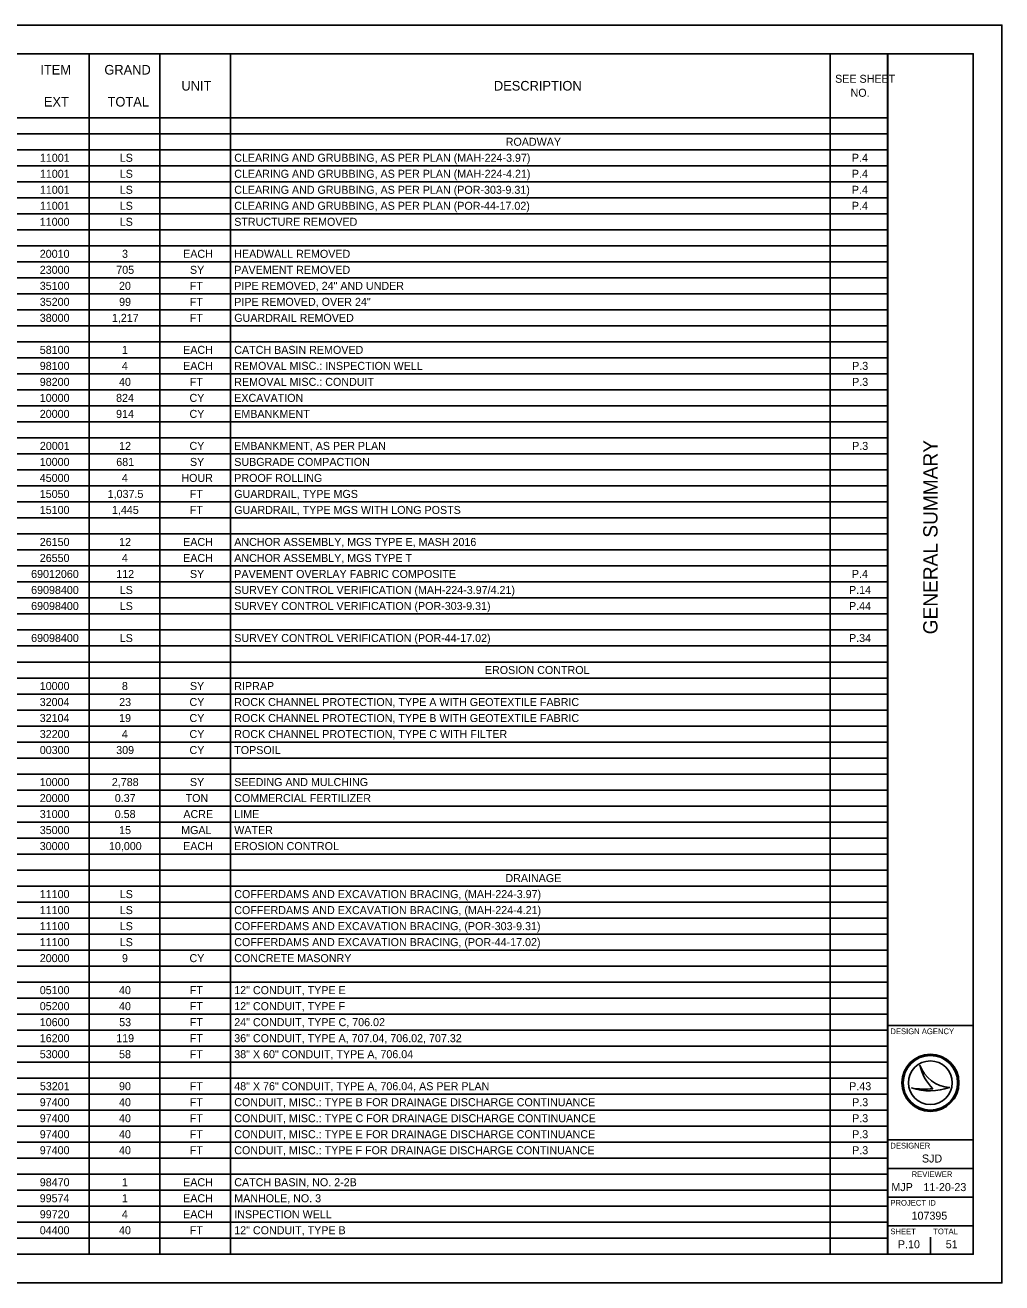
# Model space of a CAD drawing. Extents: x 0 to 34, y 0 to 22.
# Drawn here: x 16.92 to 34, y 0 to 22 of the extents above; entities that cross this region are included whole.
import ezdxf

# ---------------------------------------------------------------- set-up
doc = ezdxf.new("R2010")
doc.units = 0
for name, color, linetype in [('SH_Border', 7, 'Continuous'), ('SH_Cut_Line', 7, 'Continuous'), ('SH_Data', 7, 'Continuous'), ('SH_Text', 7, 'Continuous')]:
    doc.layers.add(name, color=color, linetype=linetype)

msp = doc.modelspace()

# ---------------------------------------------------------------- linework, layer by layer
at = {"layer": 'SH_Border'}
for p, q in [((32, 0.5), (32, 21.5)), ((32, 4.5), (33.5, 4.5)), ((32, 2.5), (33.5, 2.5)), ((32, 2), (33.5, 2)), ((32, 1.5), (33.5, 1.5)), ((32, 1), (33.5, 1))]:
    msp.add_line(p, q, dxfattribs=at)
msp.add_lwpolyline([(1.5, 21.5), (33.5, 21.5), (33.5, 0.5), (1.5, 0.5)], close=True, dxfattribs=at)
at = {"layer": 'SH_Cut_Line'}
msp.add_lwpolyline([(0, 0), (34, 0), (34, 22), (0, 22)], close=True, dxfattribs=at)
at = {"layer": 'SH_Data'}
for p, q in [((32.567, 3.81), (32.567, 3.81)), ((32.417, 3.41), (32.417, 3.41)), ((32.75, 3.5), (32.75, 3.5)), ((33.087, 3.419), (33.087, 3.419)), ((32.375, 0.675), (32.375, 0.675)), ((32.75, 0.5), (32.75, 0.8))]:
    msp.add_line(p, q, dxfattribs=at)
for radius in [0.5, 0.477, 0.477, 0.382]:
    msp.add_circle((32.75, 3.5), radius, dxfattribs=at)
for centre, radius, start, end in [((33.116, 3.998), 0.58, 198.9257, 198.9319), ((33.347, 3.97), 0.796, 191.6379, 191.6421), ((33.116, 3.998), 0.58, 198.9319, 267.1657), ((33.347, 3.97), 0.796, 191.6421, 226.0947), ((32.739, 4.37), 1.013, 251.4576, 290.0832), ((32.648, 4.654), 1.266, 259.4964, 259.4995), ((32.739, 4.37), 1.013, 251.4527, 251.4576), ((32.648, 4.654), 1.266, 259.4995, 276.6672)]:
    msp.add_arc(centre, radius, start, end, dxfattribs=at)
at = {"layer": 'SH_Text'}
for p, q in [((1.5, 21.5), (32.004, 21.5)), ((18.036, 21.5), (18.036, 0.5)), ((19.272, 21.5), (19.272, 0.5)), ((20.507, 21.5), (20.507, 0.5)), ((30.999, 21.5), (30.999, 0.5)), ((32.004, 21.5), (32.004, 0.5)), ((1.5, 20.38), (32.004, 20.38)), ((1.5, 20.1), (32.004, 20.1)), ((1.5, 19.82), (32.004, 19.82)), ((1.5, 19.54), (32.004, 19.54)), ((1.5, 19.26), (32.004, 19.26)), ((1.5, 18.98), (32.004, 18.98)), ((1.5, 18.7), (32.004, 18.7)), ((1.5, 18.42), (32.004, 18.42)), ((1.5, 18.14), (32.004, 18.14)), ((1.5, 17.86), (32.004, 17.86)), ((1.5, 17.58), (32.004, 17.58)), ((1.5, 17.3), (32.004, 17.3)), ((1.5, 17.02), (32.004, 17.02)), ((1.5, 16.74), (32.004, 16.74)), ((1.5, 16.46), (32.004, 16.46)), ((1.5, 16.18), (32.004, 16.18)), ((1.5, 15.9), (32.004, 15.9)), ((1.5, 15.62), (32.004, 15.62)), ((1.5, 15.34), (32.004, 15.34)), ((1.5, 15.06), (32.004, 15.06)), ((1.5, 14.78), (32.004, 14.78)), ((1.5, 14.5), (32.004, 14.5)), ((1.5, 14.22), (32.004, 14.22)), ((1.5, 13.94), (32.004, 13.94)), ((1.5, 13.66), (32.004, 13.66)), ((1.5, 13.38), (32.004, 13.38)), ((1.5, 13.1), (32.004, 13.1)), ((1.5, 12.82), (32.004, 12.82)), ((1.5, 12.54), (32.004, 12.54)), ((1.5, 12.26), (32.004, 12.26)), ((1.5, 11.98), (32.004, 11.98)), ((1.5, 11.7), (32.004, 11.7)), ((1.5, 11.42), (32.004, 11.42)), ((1.5, 11.14), (32.004, 11.14)), ((1.5, 10.86), (32.004, 10.86)), ((1.5, 10.58), (32.004, 10.58)), ((1.5, 10.3), (32.004, 10.3)), ((1.5, 10.02), (32.004, 10.02)), ((1.5, 9.74), (32.004, 9.74)), ((1.5, 9.46), (32.004, 9.46)), ((1.5, 9.18), (32.004, 9.18)), ((1.5, 8.9), (32.004, 8.9)), ((1.5, 8.62), (32.004, 8.62)), ((1.5, 8.34), (32.004, 8.34)), ((1.5, 8.06), (32.004, 8.06)), ((1.5, 7.78), (32.004, 7.78)), ((1.5, 7.5), (32.004, 7.5)), ((1.5, 7.22), (32.004, 7.22)), ((1.5, 6.94), (32.004, 6.94)), ((1.5, 6.66), (32.004, 6.66)), ((1.5, 6.38), (32.004, 6.38)), ((1.5, 6.1), (32.004, 6.1)), ((1.5, 5.82), (32.004, 5.82)), ((1.5, 5.54), (32.004, 5.54)), ((1.5, 5.26), (32.004, 5.26)), ((1.5, 4.98), (32.004, 4.98)), ((1.5, 4.7), (32.004, 4.7)), ((1.5, 4.42), (32.004, 4.42)), ((1.5, 4.14), (32.004, 4.14)), ((1.5, 3.86), (32.004, 3.86)), ((1.5, 3.58), (32.004, 3.58)), ((1.5, 3.3), (32.004, 3.3)), ((1.5, 3.02), (32.004, 3.02)), ((1.5, 2.74), (32.004, 2.74)), ((1.5, 2.46), (32.004, 2.46)), ((1.5, 2.18), (32.004, 2.18)), ((1.5, 1.9), (32.004, 1.9)), ((1.5, 1.62), (32.004, 1.62)), ((1.5, 1.34), (32.004, 1.34)), ((1.5, 1.06), (32.004, 1.06)), ((1.5, 0.78), (32.004, 0.78)), ((1.5, 0.5), (32.004, 0.5))]:
    msp.add_line(p, q, dxfattribs=at)

# ---------------------------------------------------------------- texts
at = {"layer": 'SH_Data'}
msp.add_text('GENERAL SUMMARY', height=0.25, rotation=90, dxfattribs=at).set_placement((32.875, 11.344))
for s, height, p in [('DESIGN AGENCY', 0.1, (32.05, 4.35)), ('DESIGNER', 0.1, (32.05, 2.35)), ('SJD', 0.14, (32.602, 2.105)), ('REVIEWER', 0.1, (32.422, 1.85)), ('MJP', 0.14, (32.068, 1.605)), ('11-20-23', 0.14, (32.629, 1.605)), ('PROJECT ID', 0.1, (32.05, 1.35)), ('107395', 0.14, (32.421, 1.105)), ('SHEET', 0.1, (32.05, 0.85)), ('TOTAL', 0.1, (32.8, 0.85)), ('P.10', 0.14, (32.182, 0.605)), ('51', 0.14, (33.019, 0.605))]:
    msp.add_text(s, height=height, dxfattribs=at).set_placement(p)
at = {"layer": 'SH_Text'}
for s, height, p in [('ITEM', 0.168, (17.181, 21.136)), ('GRAND', 0.168, (18.301, 21.136)), ('SEE SHEET ', 0.14, (31.084, 20.992)), ('UNIT', 0.168, (19.649, 20.856)), ('DESCRIPTION', 0.168, (25.115, 20.856)), ('EXT', 0.168, (17.242, 20.576)), ('TOTAL', 0.168, (18.357, 20.576)), ('NO.', 0.14, (31.354, 20.747)), ('ROADWAY', 0.14, (25.322, 19.89)), ('11001', 0.14, (17.173, 19.61)), ('LS', 0.14, (18.57, 19.61)), ('CLEARING AND GRUBBING, AS PER PLAN (MAH-224-3.97)', 0.14, (20.573, 19.61)), ('P.4', 0.14, (31.377, 19.61)), ('11001', 0.14, (17.173, 19.33)), ('LS', 0.14, (18.57, 19.33)), ('CLEARING AND GRUBBING, AS PER PLAN (MAH-224-4.21)', 0.14, (20.573, 19.33)), ('P.4', 0.14, (31.377, 19.33)), ('11001', 0.14, (17.173, 19.05)), ('LS', 0.14, (18.57, 19.05)), ('CLEARING AND GRUBBING, AS PER PLAN (POR-303-9.31)', 0.14, (20.573, 19.05)), ('P.4', 0.14, (31.377, 19.05)), ('11001', 0.14, (17.173, 18.77)), ('LS', 0.14, (18.57, 18.77)), ('CLEARING AND GRUBBING, AS PER PLAN (POR-44-17.02)', 0.14, (20.573, 18.77)), ('P.4', 0.14, (31.377, 18.77)), ('11000', 0.14, (17.171, 18.49)), ('LS', 0.14, (18.57, 18.49)), ('STRUCTURE REMOVED', 0.14, (20.573, 18.49)), ('20010', 0.14, (17.171, 17.93)), ('3', 0.14, (18.61, 17.93)), ('EACH', 0.14, (19.679, 17.93)), ('HEADWALL REMOVED', 0.14, (20.573, 17.93)), ('23000', 0.14, (17.171, 17.65)), ('705', 0.14, (18.509, 17.65)), ('SY', 0.14, (19.798, 17.65)), ('PAVEMENT REMOVED', 0.14, (20.573, 17.65)), ('35100', 0.14, (17.171, 17.37)), ('20', 0.14, (18.557, 17.37)), ('FT', 0.14, (19.796, 17.37)), ('PIPE REMOVED, 24" AND UNDER', 0.14, (20.573, 17.37)), ('35200', 0.14, (17.171, 17.09)), ('99', 0.14, (18.559, 17.09)), ('FT', 0.14, (19.796, 17.09)), ('PIPE REMOVED, OVER 24"', 0.14, (20.573, 17.09)), ('38000', 0.14, (17.171, 16.81)), ('1,217', 0.14, (18.433, 16.81)), ('FT', 0.14, (19.796, 16.81)), ('GUARDRAIL REMOVED', 0.14, (20.573, 16.81)), ('58100', 0.14, (17.171, 16.25)), ('1', 0.14, (18.609, 16.25)), ('EACH', 0.14, (19.679, 16.25)), ('CATCH BASIN REMOVED', 0.14, (20.573, 16.25)), ('98100', 0.14, (17.171, 15.97)), ('4', 0.14, (18.607, 15.97)), ('EACH', 0.14, (19.679, 15.97)), ('REMOVAL MISC.: INSPECTION WELL', 0.14, (20.573, 15.97)), ('P.3', 0.14, (31.381, 15.97)), ('98200', 0.14, (17.171, 15.69)), ('40', 0.14, (18.557, 15.69)), ('FT', 0.14, (19.796, 15.69)), ('REMOVAL MISC.: CONDUIT', 0.14, (20.573, 15.69)), ('P.3', 0.14, (31.381, 15.69)), ('10000', 0.14, (17.171, 15.41)), ('824', 0.14, (18.506, 15.41)), ('CY', 0.14, (19.79, 15.41)), ('EXCAVATION', 0.14, (20.573, 15.41)), ('20000', 0.14, (17.171, 15.13)), ('914', 0.14, (18.506, 15.13)), ('CY', 0.14, (19.79, 15.13)), ('EMBANKMENT', 0.14, (20.573, 15.13)), ('20001', 0.14, (17.173, 14.57)), ('12', 0.14, (18.559, 14.57)), ('CY', 0.14, (19.79, 14.57)), ('EMBANKMENT, AS PER PLAN', 0.14, (20.573, 14.57)), ('P.3', 0.14, (31.381, 14.57)), ('10000', 0.14, (17.171, 14.29)), ('681', 0.14, (18.509, 14.29)), ('SY', 0.14, (19.798, 14.29)), ('SUBGRADE COMPACTION', 0.14, (20.573, 14.29)), ('45000', 0.14, (17.171, 14.01)), ('4', 0.14, (18.607, 14.01)), ('HOUR', 0.14, (19.648, 14.01)), ('PROOF ROLLING', 0.14, (20.573, 14.01)), ('15050', 0.14, (17.171, 13.73)), ('1,037.5', 0.14, (18.359, 13.73)), ('FT', 0.14, (19.796, 13.73)), ('GUARDRAIL, TYPE MGS', 0.14, (20.573, 13.73)), ('15100', 0.14, (17.171, 13.45)), ('1,445', 0.14, (18.434, 13.45)), ('FT', 0.14, (19.796, 13.45)), ('GUARDRAIL, TYPE MGS WITH LONG POSTS', 0.14, (20.573, 13.45)), ('26150', 0.14, (17.171, 12.89)), ('12', 0.14, (18.559, 12.89)), ('EACH', 0.14, (19.679, 12.89)), ('ANCHOR ASSEMBLY, MGS TYPE E, MASH 2016', 0.14, (20.573, 12.89)), ('26550', 0.14, (17.171, 12.61)), ('4', 0.14, (18.607, 12.61)), ('EACH', 0.14, (19.679, 12.61)), ('ANCHOR ASSEMBLY, MGS TYPE T', 0.14, (20.573, 12.61)), ('69012060', 0.14, (17.02, 12.33)), ('112', 0.14, (18.509, 12.33)), ('SY', 0.14, (19.798, 12.33)), ('PAVEMENT OVERLAY FABRIC COMPOSITE', 0.14, (20.573, 12.33)), ('P.4', 0.14, (31.377, 12.33)), ('69098400', 0.14, (17.02, 12.05)), ('LS', 0.14, (18.57, 12.05)), ('SURVEY CONTROL VERIFICATION (MAH-224-3.97/4.21)', 0.14, (20.573, 12.05)), ('P.14', 0.14, (31.327, 12.05)), ('69098400', 0.14, (17.02, 11.77)), ('LS', 0.14, (18.57, 11.77)), ('SURVEY CONTROL VERIFICATION (POR-303-9.31)', 0.14, (20.573, 11.77)), ('P.44', 0.14, (31.327, 11.77)), ('69098400', 0.14, (17.02, 11.21)), ('LS', 0.14, (18.57, 11.21)), ('SURVEY CONTROL VERIFICATION (POR-44-17.02)', 0.14, (20.573, 11.21)), ('P.34', 0.14, (31.327, 11.21)), ('EROSION CONTROL', 0.14, (24.957, 10.65)), ('10000', 0.14, (17.171, 10.37)), ('8', 0.14, (18.608, 10.37)), ('SY', 0.14, (19.798, 10.37)), ('RIPRAP', 0.14, (20.573, 10.37)), ('32004', 0.14, (17.17, 10.09)), ('23', 0.14, (18.56, 10.09)), ('CY', 0.14, (19.79, 10.09)), ('ROCK CHANNEL PROTECTION, TYPE A WITH GEOTEXTILE FABRIC', 0.14, (20.573, 10.09)), ('32104', 0.14, (17.17, 9.81)), ('19', 0.14, (18.559, 9.81)), ('CY', 0.14, (19.79, 9.81)), ('ROCK CHANNEL PROTECTION, TYPE B WITH GEOTEXTILE FABRIC', 0.14, (20.573, 9.81)), ('32200', 0.14, (17.171, 9.53)), ('4', 0.14, (18.607, 9.53)), ('CY', 0.14, (19.79, 9.53)), ('ROCK CHANNEL PROTECTION, TYPE C WITH FILTER', 0.14, (20.573, 9.53)), ('00300', 0.14, (17.171, 9.25)), ('309', 0.14, (18.508, 9.25)), ('CY', 0.14, (19.79, 9.25)), ('TOPSOIL', 0.14, (20.573, 9.25)), ('10000', 0.14, (17.171, 8.69)), ('2,788', 0.14, (18.432, 8.69)), ('SY', 0.14, (19.798, 8.69)), ('SEEDING AND MULCHING', 0.14, (20.573, 8.69)), ('20000', 0.14, (17.171, 8.41)), ('0.37', 0.14, (18.483, 8.41)), ('TON', 0.14, (19.722, 8.41)), ('COMMERCIAL FERTILIZER', 0.14, (20.573, 8.41)), ('31000', 0.14, (17.171, 8.13)), ('0.58', 0.14, (18.482, 8.13)), ('ACRE', 0.14, (19.683, 8.13)), ('LIME', 0.14, (20.573, 8.13)), ('35000', 0.14, (17.171, 7.85)), ('15', 0.14, (18.559, 7.85)), ('MGAL', 0.14, (19.644, 7.85)), ('WATER', 0.14, (20.573, 7.85)), ('30000', 0.14, (17.171, 7.57)), ('10,000', 0.14, (18.381, 7.57)), ('EACH', 0.14, (19.679, 7.57)), ('EROSION CONTROL', 0.14, (20.573, 7.57)), ('DRAINAGE', 0.14, (25.316, 7.01)), ('11100', 0.14, (17.171, 6.73)), ('LS', 0.14, (18.57, 6.73)), ('COFFERDAMS AND EXCAVATION BRACING, (MAH-224-3.97)', 0.14, (20.573, 6.73)), ('11100', 0.14, (17.171, 6.45)), ('LS', 0.14, (18.57, 6.45)), ('COFFERDAMS AND EXCAVATION BRACING, (MAH-224-4.21)', 0.14, (20.573, 6.45)), ('11100', 0.14, (17.171, 6.17)), ('LS', 0.14, (18.57, 6.17)), ('COFFERDAMS AND EXCAVATION BRACING, (POR-303-9.31)', 0.14, (20.573, 6.17)), ('11100', 0.14, (17.171, 5.89)), ('LS', 0.14, (18.57, 5.89)), ('COFFERDAMS AND EXCAVATION BRACING, (POR-44-17.02)', 0.14, (20.573, 5.89)), ('20000', 0.14, (17.171, 5.61)), ('9', 0.14, (18.609, 5.61)), ('CY', 0.14, (19.79, 5.61)), ('CONCRETE MASONRY', 0.14, (20.573, 5.61)), ('05100', 0.14, (17.171, 5.05)), ('40', 0.14, (18.557, 5.05)), ('FT', 0.14, (19.796, 5.05)), ('12" CONDUIT, TYPE E', 0.14, (20.573, 5.05)), ('05200', 0.14, (17.171, 4.77)), ('40', 0.14, (18.557, 4.77)), ('FT', 0.14, (19.796, 4.77)), ('12" CONDUIT, TYPE F', 0.14, (20.573, 4.77)), ('10600', 0.14, (17.171, 4.49)), ('53', 0.14, (18.56, 4.49)), ('FT', 0.14, (19.796, 4.49)), ('24" CONDUIT, TYPE C, 706.02', 0.14, (20.573, 4.49)), ('16200', 0.14, (17.171, 4.21)), ('119', 0.14, (18.508, 4.21)), ('FT', 0.14, (19.796, 4.21)), ('36" CONDUIT, TYPE A, 707.04, 706.02, 707.32', 0.14, (20.573, 4.21)), ('53000', 0.14, (17.171, 3.93)), ('58', 0.14, (18.558, 3.93)), ('FT', 0.14, (19.796, 3.93)), ('38" X 60" CONDUIT, TYPE A, 706.04', 0.14, (20.573, 3.93)), ('53201', 0.14, (17.173, 3.37)), ('90', 0.14, (18.557, 3.37)), ('FT', 0.14, (19.796, 3.37)), ('48" X 76" CONDUIT, TYPE A, 706.04, AS PER PLAN', 0.14, (20.573, 3.37)), ('P.43', 0.14, (31.33, 3.37)), ('97400', 0.14, (17.171, 3.09)), ('40', 0.14, (18.557, 3.09)), ('FT', 0.14, (19.796, 3.09)), ('CONDUIT, MISC.: TYPE B FOR DRAINAGE DISCHARGE CONTINUANCE', 0.14, (20.573, 3.09)), ('P.3', 0.14, (31.381, 3.09)), ('97400', 0.14, (17.171, 2.81)), ('40', 0.14, (18.557, 2.81)), ('FT', 0.14, (19.796, 2.81)), ('CONDUIT, MISC.: TYPE C FOR DRAINAGE DISCHARGE CONTINUANCE', 0.14, (20.573, 2.81)), ('P.3', 0.14, (31.381, 2.81)), ('97400', 0.14, (17.171, 2.53)), ('40', 0.14, (18.557, 2.53)), ('FT', 0.14, (19.796, 2.53)), ('CONDUIT, MISC.: TYPE E FOR DRAINAGE DISCHARGE CONTINUANCE', 0.14, (20.573, 2.53)), ('P.3', 0.14, (31.381, 2.53)), ('97400', 0.14, (17.171, 2.25)), ('40', 0.14, (18.557, 2.25)), ('FT', 0.14, (19.796, 2.25)), ('CONDUIT, MISC.: TYPE F FOR DRAINAGE DISCHARGE CONTINUANCE', 0.14, (20.573, 2.25)), ('P.3', 0.14, (31.381, 2.25)), ('98470', 0.14, (17.171, 1.69)), ('1', 0.14, (18.609, 1.69)), ('EACH', 0.14, (19.679, 1.69)), ('CATCH BASIN, NO. 2-2B', 0.14, (20.573, 1.69)), ('99574', 0.14, (17.17, 1.41)), ('1', 0.14, (18.609, 1.41)), ('EACH', 0.14, (19.679, 1.41)), ('MANHOLE, NO. 3', 0.14, (20.573, 1.41)), ('99720', 0.14, (17.171, 1.13)), ('4', 0.14, (18.607, 1.13)), ('EACH', 0.14, (19.679, 1.13)), ('INSPECTION WELL', 0.14, (20.573, 1.13)), ('04400', 0.14, (17.171, 0.85)), ('40', 0.14, (18.557, 0.85)), ('FT', 0.14, (19.796, 0.85)), ('12" CONDUIT, TYPE B', 0.14, (20.573, 0.85))]:
    msp.add_text(s, height=height, dxfattribs=at).set_placement(p)

doc.saveas('drawing.dxf')
